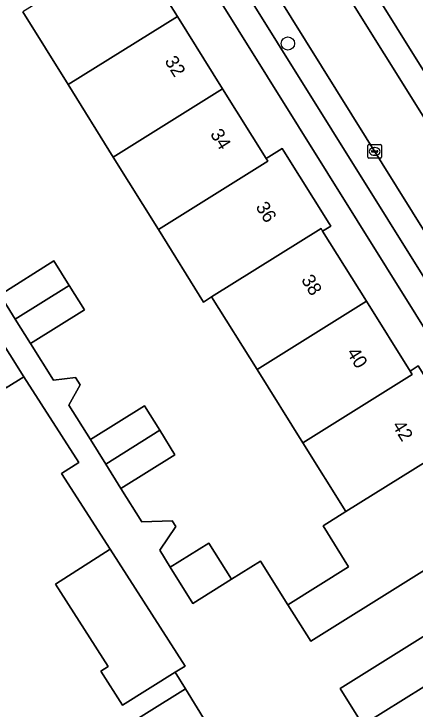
# Model space of a CAD drawing. Extents: x 159664 to 160323, y 385312 to 386115.
# Drawn here: x 159789.6 to 159819.3, y 385757.3 to 385808.6 of the extents above; entities that cross this region are included whole.
import ezdxf

# ---------------------------------------------------------------- set-up
doc = ezdxf.new("R2010")
doc.units = 0
for name, color, linetype in [('IMGEO_Boom', 7, 'Continuous'), ('IMGEO_Erf', 7, 'Continuous'), ('IMGEO_Kolk', 7, 'Continuous'), ('IMGEO_Pand', 7, 'Continuous'), ('IMGEO_Pand_nummerreeks', 7, 'Continuous'), ('IMGEO_Parkeervlak_open', 7, 'Continuous'), ('IMGEO_Rijbaan_lokaal_open', 7, 'Continuous'), ('IMGEO_Voetpad_open', 7, 'Continuous')]:
    doc.layers.add(name, color=color, linetype=linetype)

msp = doc.modelspace()

# ---------------------------------------------------------------- linework, layer by layer
at = {"layer": 'IMGEO_Boom'}
msp.add_circle((159809.875, 385806.434), 0.489, dxfattribs=at)
at = {"layer": 'IMGEO_Erf'}
for points in [[(159798.487, 385813.604), (159801.717, 385808.436), (159805.055, 385803.087), (159808.273, 385797.942), (159809.46, 385798.684), (159809.583, 385798.487), (159812.917, 385793.151), (159813.028, 385792.974), (159812.434, 385792.603), (159815.668, 385787.428), (159818.887, 385782.278), (159819.48, 385782.649), (159819.646, 385782.385), (159822.817, 385777.31), (159823.045, 385776.946), (159822.451, 385776.575), (159825.789, 385771.227), (159827.962, 385772.584), (159791.049, 385831.741)], [(159788.616, 385787.906), (159792.603, 385790.394), (159793.727, 385788.593), (159794.85, 385786.792), (159790.863, 385784.305), (159792.581, 385781.613), (159794.19, 385781.797), (159794.544, 385781.258), (159793.708, 385779.76), (159795.297, 385777.218), (159799.282, 385779.709), (159800.409, 385777.908), (159801.536, 385776.106), (159797.551, 385773.614), (159799.084, 385771.163), (159801.34, 385771.236), (159801.594, 385770.819), (159800.421, 385769.056), (159801.187, 385767.798), (159804.038, 385769.577), (159805.7, 385766.913), (159807.854, 385768.257), (159809.877, 385765.026), (159814.352, 385767.828), (159812.463, 385770.845), (159814.159, 385771.908), (159810.983, 385776.98), (159807.594, 385782.391), (159804.243, 385787.739), (159803.65, 385787.367), (159800.321, 385792.708), (159796.988, 385798.054), (159793.651, 385803.403), (159790.298, 385808.779)], [(159796.56, 385755.247), (159802.309, 385758.834), (159801.55, 385760.062), (159797.656, 385757.639), (159796.059, 385760.128), (159796.615, 385760.485), (159792.723, 385766.553), (159796.748, 385769.135), (159793.172, 385774.709), (159794.438, 385775.521), (159790.372, 385781.858), (159789.083, 385781.046), (159783.535, 385777.552), (159778.24, 385785.96), (159753.983, 385770.681), (159766.915, 385750)]]:
    msp.add_lwpolyline(points, dxfattribs=at)
msp.add_lwpolyline([(159830.036, 385746.522), (159826.72, 385751.836), (159823.479, 385757.029), (159823.404, 385757.149), (159821.707, 385756.093), (159819.895, 385758.985), (159815.411, 385756.178), (159816.859, 385753.82), (159810.035, 385749.593), (159809.719, 385747.405), (159811.745, 385744.284), (159813.611, 385744.153), (159813.959, 385743.68), (159813.218, 385741.755), (159814.676, 385739.428), (159818.659, 385741.923), (159819.793, 385740.114), (159820.927, 385738.304), (159816.944, 385735.809), (159819.262, 385732.102), (159833.484, 385740.995)], close=True, dxfattribs=at)
at = {"layer": 'IMGEO_Kolk'}
for p, q in [((159815.772, 385798.05), (159815.772, 385798.902)), ((159815.847, 385798.976), (159816.699, 385798.976)), ((159816.26, 385798.756), (159816.285, 385798.756)), ((159816.773, 385798.902), (159816.773, 385798.05)), ((159816.031, 385798.47), (159816.031, 385798.482)), ((159816.469, 385798.433), (159816.071, 385798.433)), ((159816.074, 385798.519), (159816.472, 385798.519)), ((159816.283, 385798.196), (159816.258, 385798.196)), ((159816.515, 385798.482), (159816.515, 385798.47)), ((159816.699, 385797.976), (159815.847, 385797.976))]:
    msp.add_line(p, q, dxfattribs=at)
for points in [[(159815.772, 385798.05), (159815.772, 385798.902)], [(159815.847, 385798.976), (159816.699, 385798.976)], [(159816.773, 385798.902), (159816.773, 385798.05)], [(159816.699, 385797.976), (159815.847, 385797.976)]]:
    msp.add_lwpolyline(points, dxfattribs=at)
for centre, radius, start, end in [((159815.849, 385798.9), 0.0765, 91.552, 178.448), ((159815.849, 385798.9), 0.0765, 91.552, 178.448), ((159816.697, 385798.9), 0.0765, 1.552, 88.448), ((159816.697, 385798.9), 0.0765, 1.552, 88.448), ((159815.849, 385798.052), 0.0765, 181.552, 268.448), ((159815.849, 385798.052), 0.0765, 181.552, 268.448), ((159816.071, 385798.479), 0.0403, 85.8775, 175.7526), ((159816.068, 385798.469), 0.0366, 178.938, 274.7102), ((159816.472, 385798.476), 0.043, 264.8664, 352.4533), ((159816.476, 385798.481), 0.0386, 1.7309, 96.639), ((159816.697, 385798.052), 0.0765, 271.552, 358.448), ((159816.697, 385798.052), 0.0765, 271.552, 358.448)]:
    msp.add_arc(centre, radius, start, end, dxfattribs=at)
for centre, major_axis, ratio, start_param, end_param in [((159816.259, 385798.476), (-0.387, 0.002), 0.722429, 4.712389, 7.853982), ((159816.284, 385798.476), (-0.39, 0.002), 0.717154, 1.570796, 4.712389)]:
    msp.add_ellipse(centre, major_axis=major_axis, ratio=ratio, start_param=start_param, end_param=end_param, dxfattribs=at)
at = {"layer": 'IMGEO_Pand'}
for points in [[(159798.487, 385813.604), (159798.37, 385813.791), (159790.298, 385808.779), (159793.651, 385803.403), (159801.717, 385808.436)], [(159793.651, 385803.403), (159796.988, 385798.054), (159805.055, 385803.087), (159801.717, 385808.436)], [(159808.273, 385797.942), (159805.055, 385803.087), (159796.988, 385798.054), (159800.321, 385792.708), (159808.396, 385797.746)], [(159812.434, 385792.603), (159813.028, 385792.974), (159812.917, 385793.151), (159809.583, 385798.487), (159809.46, 385798.684), (159808.273, 385797.942), (159808.396, 385797.746), (159800.321, 385792.708), (159803.65, 385787.367), (159804.243, 385787.739), (159812.323, 385792.78)], [(159812.434, 385792.603), (159812.323, 385792.78), (159804.243, 385787.739), (159807.594, 385782.391), (159815.668, 385787.428)], [(159792.603, 385790.394), (159788.616, 385787.906), (159789.739, 385786.105), (159793.727, 385788.593)], [(159794.85, 385786.792), (159793.727, 385788.593), (159789.739, 385786.105), (159790.863, 385784.305)], [(159818.887, 385782.278), (159815.668, 385787.428), (159807.594, 385782.391), (159810.983, 385776.98), (159819.052, 385782.014)], [(159822.817, 385777.31), (159819.646, 385782.385), (159819.48, 385782.649), (159818.887, 385782.278), (159819.052, 385782.014), (159810.983, 385776.98), (159814.159, 385771.908), (159822.223, 385776.94), (159822.451, 385776.575), (159823.045, 385776.946)], [(159799.282, 385779.709), (159795.297, 385777.218), (159796.424, 385775.416), (159800.409, 385777.908)], [(159797.551, 385773.614), (159801.536, 385776.106), (159800.409, 385777.908), (159796.424, 385775.416)], [(159825.789, 385771.227), (159822.451, 385776.575), (159822.223, 385776.94), (159814.159, 385771.908), (159812.463, 385770.845), (159814.352, 385767.828), (159809.877, 385765.026), (159811.56, 385762.339)], [(159805.7, 385766.913), (159804.038, 385769.577), (159801.187, 385767.798), (159802.85, 385765.134)], [(159796.748, 385769.135), (159792.723, 385766.553), (159796.615, 385760.485), (159796.059, 385760.128), (159797.656, 385757.639), (159801.55, 385760.062), (159802.278, 385760.515)], [(159831.457, 385762.161), (159827.963, 385767.758), (159813.729, 385758.865), (159815.411, 385756.178), (159819.895, 385758.985), (159821.707, 385756.093), (159823.404, 385757.149)], [(159804.508, 385755.279), (159802.309, 385758.834), (159796.56, 385755.247), (159801.753, 385747.272), (159802.424, 385746.242), (159805.978, 385748.556), (159807.612, 385749.62), (159806.941, 385750.65), (159804.1, 385755.013)]]:
    msp.add_lwpolyline(points, close=True, dxfattribs=at)
at = {"layer": 'IMGEO_Parkeervlak_open'}
for points in [[(159741.034, 385915.456), (159751.377, 385898.907), (159753.743, 385895.078), (159790.443, 385836.375), (159792.83, 385832.57), (159829.402, 385773.998), (159831.787, 385770.18), (159850.746, 385739.72), (159852.33, 385740.71), (159841.328, 385758.304), (159807.874, 385811.971), (159785.139, 385848.258)], [(159788.888, 385850.614), (159845.062, 385760.744)], [(159836.21, 385778.296), (159799.599, 385836.908)]]:
    msp.add_lwpolyline(points, dxfattribs=at)
at = {"layer": 'IMGEO_Rijbaan_lokaal_open'}
msp.add_lwpolyline([(159788.888, 385850.614), (159785.139, 385848.258), (159807.874, 385811.971), (159841.328, 385758.304), (159845.062, 385760.744)], close=True, dxfattribs=at)
at = {"layer": 'IMGEO_Voetpad_open'}
for points in [[(159747.851, 385919.727), (159758.184, 385903.198), (159758.579, 385903.421), (159760.952, 385899.606), (159760.579, 385899.376), (159797.238, 385840.688), (159797.62, 385840.926), (159799.98, 385837.147), (159799.599, 385836.908), (159836.21, 385778.296), (159836.589, 385778.536), (159839.001, 385774.716), (159838.62, 385774.468), (159844.984, 385764.305)], [(159741.032, 385918.933), (159740.787, 385919.315), (159737.177, 385917.789), (159749.768, 385897.575), (159749.851, 385897.63), (159751.956, 385894.264), (159788.93, 385835.134), (159789.958, 385833.49), (159791.049, 385831.741), (159827.962, 385772.584), (159830.13, 385769.11), (159843.706, 385747.354)], [(159850.746, 385739.72), (159831.787, 385770.18), (159831.417, 385769.944), (159829.035, 385773.762), (159829.402, 385773.998), (159792.83, 385832.57), (159792.452, 385832.313), (159790.073, 385836.148), (159790.443, 385836.375), (159753.743, 385895.078), (159753.361, 385894.84), (159750.98, 385898.656), (159751.377, 385898.907), (159741.034, 385915.456)], [(159775.161, 385806.096), (159790.372, 385781.858), (159794.438, 385775.521), (159793.172, 385774.709), (159796.748, 385769.135), (159802.278, 385760.515), (159801.55, 385760.062), (159802.309, 385758.834), (159804.508, 385755.279)], [(159825.789, 385771.227), (159811.56, 385762.339), (159809.877, 385765.026), (159807.854, 385768.257), (159805.7, 385766.913), (159802.85, 385765.134), (159801.187, 385767.798), (159800.421, 385769.056), (159801.594, 385770.819), (159801.34, 385771.236), (159799.084, 385771.163), (159797.551, 385773.614), (159796.424, 385775.416), (159795.297, 385777.218), (159793.708, 385779.76), (159794.544, 385781.258), (159794.19, 385781.797), (159792.581, 385781.613), (159790.863, 385784.305), (159789.739, 385786.105), (159788.616, 385787.906)], [(159815.411, 385756.178), (159813.729, 385758.865), (159827.963, 385767.758)]]:
    msp.add_lwpolyline(points, dxfattribs=at)
msp.add_lwpolyline([(159775.161, 385806.096), (159773.707, 385805.242), (159782.979, 385790.896), (159776.451, 385786.658), (159771.727, 385783.591), (159753.159, 385772), (159753.16, 385771.998), (159753.983, 385770.681), (159778.24, 385785.96), (159783.787, 385789.454), (159789.083, 385781.046), (159790.372, 385781.858)], close=True, dxfattribs=at)

# ---------------------------------------------------------------- texts
at = {"layer": 'IMGEO_Pand_nummerreeks'}
for s, rotation, p in [('32', 301.9895, (159800.74, 385805.14)), ('34', 301.988, (159804.101, 385799.761)), ('36', 301.988, (159807.459, 385794.384)), ('38', 301.988, (159810.819, 385789.006)), ('40', 301.988, (159814.177, 385783.629)), ('42', 301.988, (159817.532, 385778.258))]:
    msp.add_text(s, height=1, rotation=rotation, dxfattribs=at).set_placement(p)

doc.saveas('drawing.dxf')
